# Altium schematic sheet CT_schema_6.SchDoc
size 403 x 220 mm
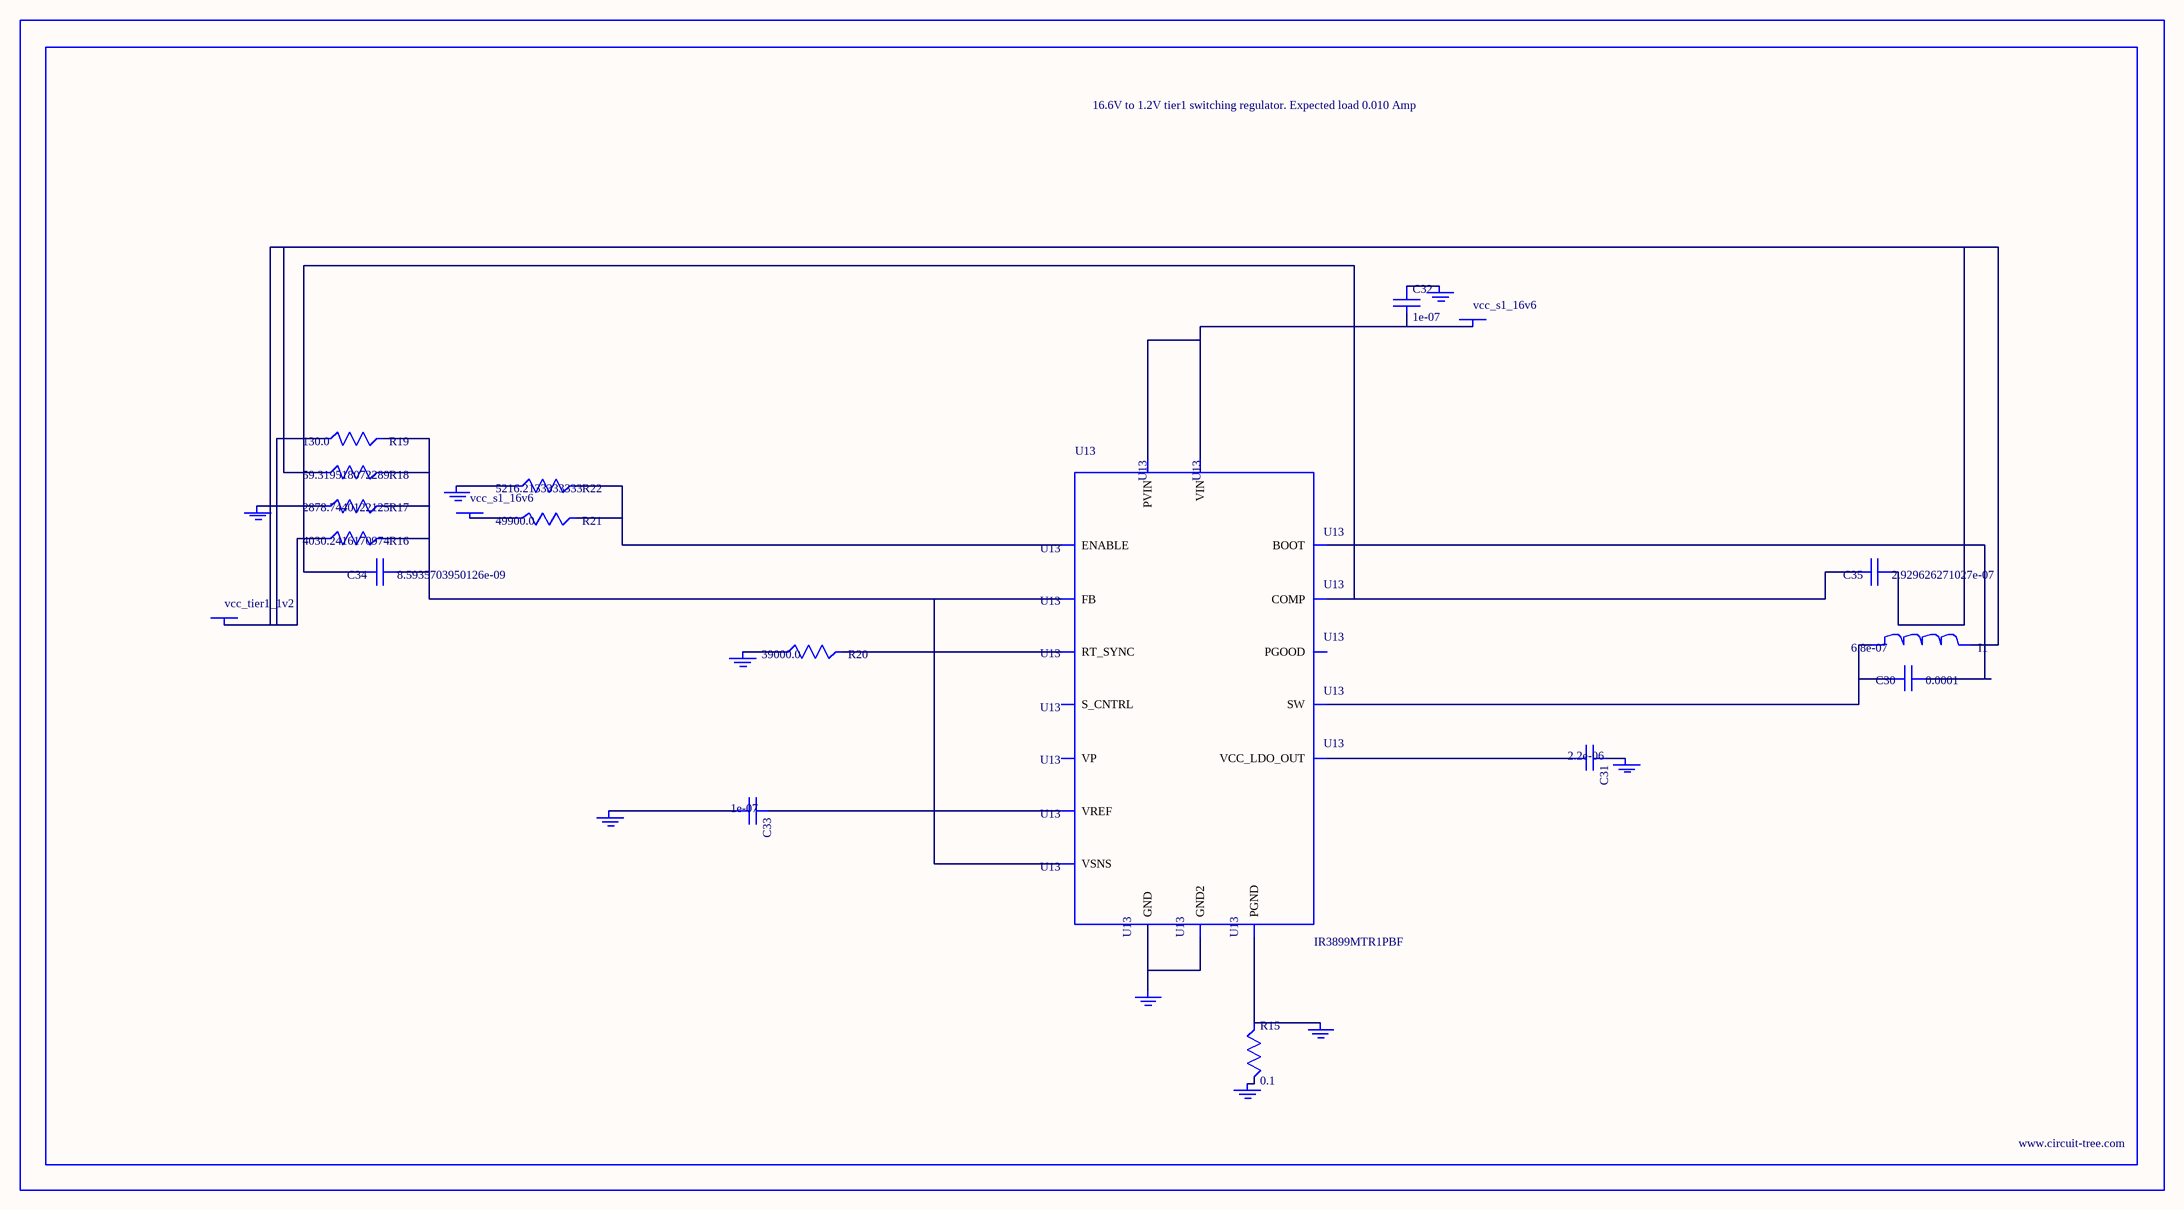
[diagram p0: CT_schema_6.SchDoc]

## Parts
BORDER5  (no value)
C30  0.0001  [C1210]
C31  2.2e-06  [C0603]
C32  1e-07  [C0402]
C33  1e-07  [C0402]
C34  8.5935703950126e-09  [R0603]
C35  2.929626271027e-07  [R0603]
GND_INSTANCE_5_0  (no value)
GND_INSTANCE_5_1  (no value)
GND_INSTANCE_5_2  (no value)
GND_INSTANCE_5_3  (no value)
GND_INSTANCE_5_4  (no value)
GND_INSTANCE_5_5  (no value)
GND_INSTANCE_5_6  (no value)
GND_INSTANCE_5_7  (no value)
GND_INSTANCE_5_8  (no value)
I1  6.8e-07  [IND25X25CZ]
POWER_INSTANCE_5_0  vcc_s1_16v6
POWER_INSTANCE_5_1  vcc_s1_16v6
POWER_INSTANCE_5_2  vcc_tier1_1v2
R15  0.1  [R0603]
R16  4030.2416170974  [R0603]
R17  2878.7440122125  [R0603]
R18  59.319518072289  [R0603]
R19  130.0  [R0603]
R20  39000.0  [R0603]
R21  49900.0  [R0603]
R22  5216.2133333333  [R0603]
U13  IR3899MTR1PBF  [IR3899MTR1PBF]

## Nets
NetC30_1: C30.1 U13.14(BOOT)
NetC30_2: C30.2 I1.1 U13.12(SW)
NetC31_1: C31.1 GND_INSTANCE_5_4.0(GND)
NetC31_2: C31.2 U13.10(VCC_LDO_OUT)
NetC32_1: C32.1 GND_INSTANCE_5_3.0(GND)
NetC32_2: C32.2 POWER_INSTANCE_5_0.0(PWR) U13.9(VIN) U13.13(PVIN)
NetC33_1: C33.1 U13.2(VREF)
NetC33_2: C33.2 GND_INSTANCE_5_1.0(GND)
NetC34_1: C34.1 R16.2 R17.2 R18.2 R19.2 U13.1(FB) U13.8(VSNS)
NetC34_2: C34.2 C35.2 U13.3(COMP)
NetC35_1: C35.1 I1.2 POWER_INSTANCE_5_2.0(PWR) R16.1 R18.1 R19.1
NetGND_INSTANCE_5_0_0: GND_INSTANCE_5_0.0(GND) R17.1
NetGND_INSTANCE_5_2_0: GND_INSTANCE_5_2.0(GND) R20.1
NetGND_INSTANCE_5_5_0: GND_INSTANCE_5_5.0(GND) R15.2
NetGND_INSTANCE_5_6_0: GND_INSTANCE_5_6.0(GND) R15.1 U13.11(PGND)
NetGND_INSTANCE_5_7_0: GND_INSTANCE_5_7.0(GND) R22.1
NetGND_INSTANCE_5_8_0: GND_INSTANCE_5_8.0(GND) U13.4(GND) U13.17(GND2)
NetPOWER_INSTANCE_5_1_0: POWER_INSTANCE_5_1.0(PWR) R21.1
NetR20_2: R20.2 U13.5(RT_SYNC)
NetR21_2: R21.2 R22.2 U13.15(ENABLE)

Not connected (* = marked no-connect by the designer): U13 6(S_CNTRL) 7(PGOOD) 16(VP)

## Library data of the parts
BORDER5 = BORDER_PAGE5
C30 = GRM32ER61A107ME20L
C31 = C0603C225K8RACTU
C32 C33 = C0402C104K3RACTU
C34 = C34
C35 = C35
GND_INSTANCE_5_0-GND_INSTANCE_5_8 = GND
I1 = IHLP2525CZERR68M01
POWER_INSTANCE_5_0-POWER_INSTANCE_5_2 = PWR
R15 = ERJ-3RSFR10V
R16 = R16
R17 = R17
R18 = R18
R19 = RC0603JR-07130RL
R20 = RC0603JR-0739KL
R21 = RC0603FR-0749K9
R22 = R22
